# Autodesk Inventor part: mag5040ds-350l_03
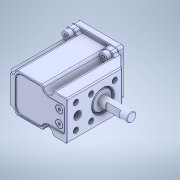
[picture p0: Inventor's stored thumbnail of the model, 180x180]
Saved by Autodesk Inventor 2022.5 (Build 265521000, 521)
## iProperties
Created: 2023-04
Part Number: mag5040ds-350l_03
Material: Generic
Document SubType Name: Modeling
Designer: ImaoCorp
Density: 1 g/cm^3
Appearance: Default
Author: ImaoCorp
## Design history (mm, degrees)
feature "mag5040ds-350l_03"
node "ソリッド1"
